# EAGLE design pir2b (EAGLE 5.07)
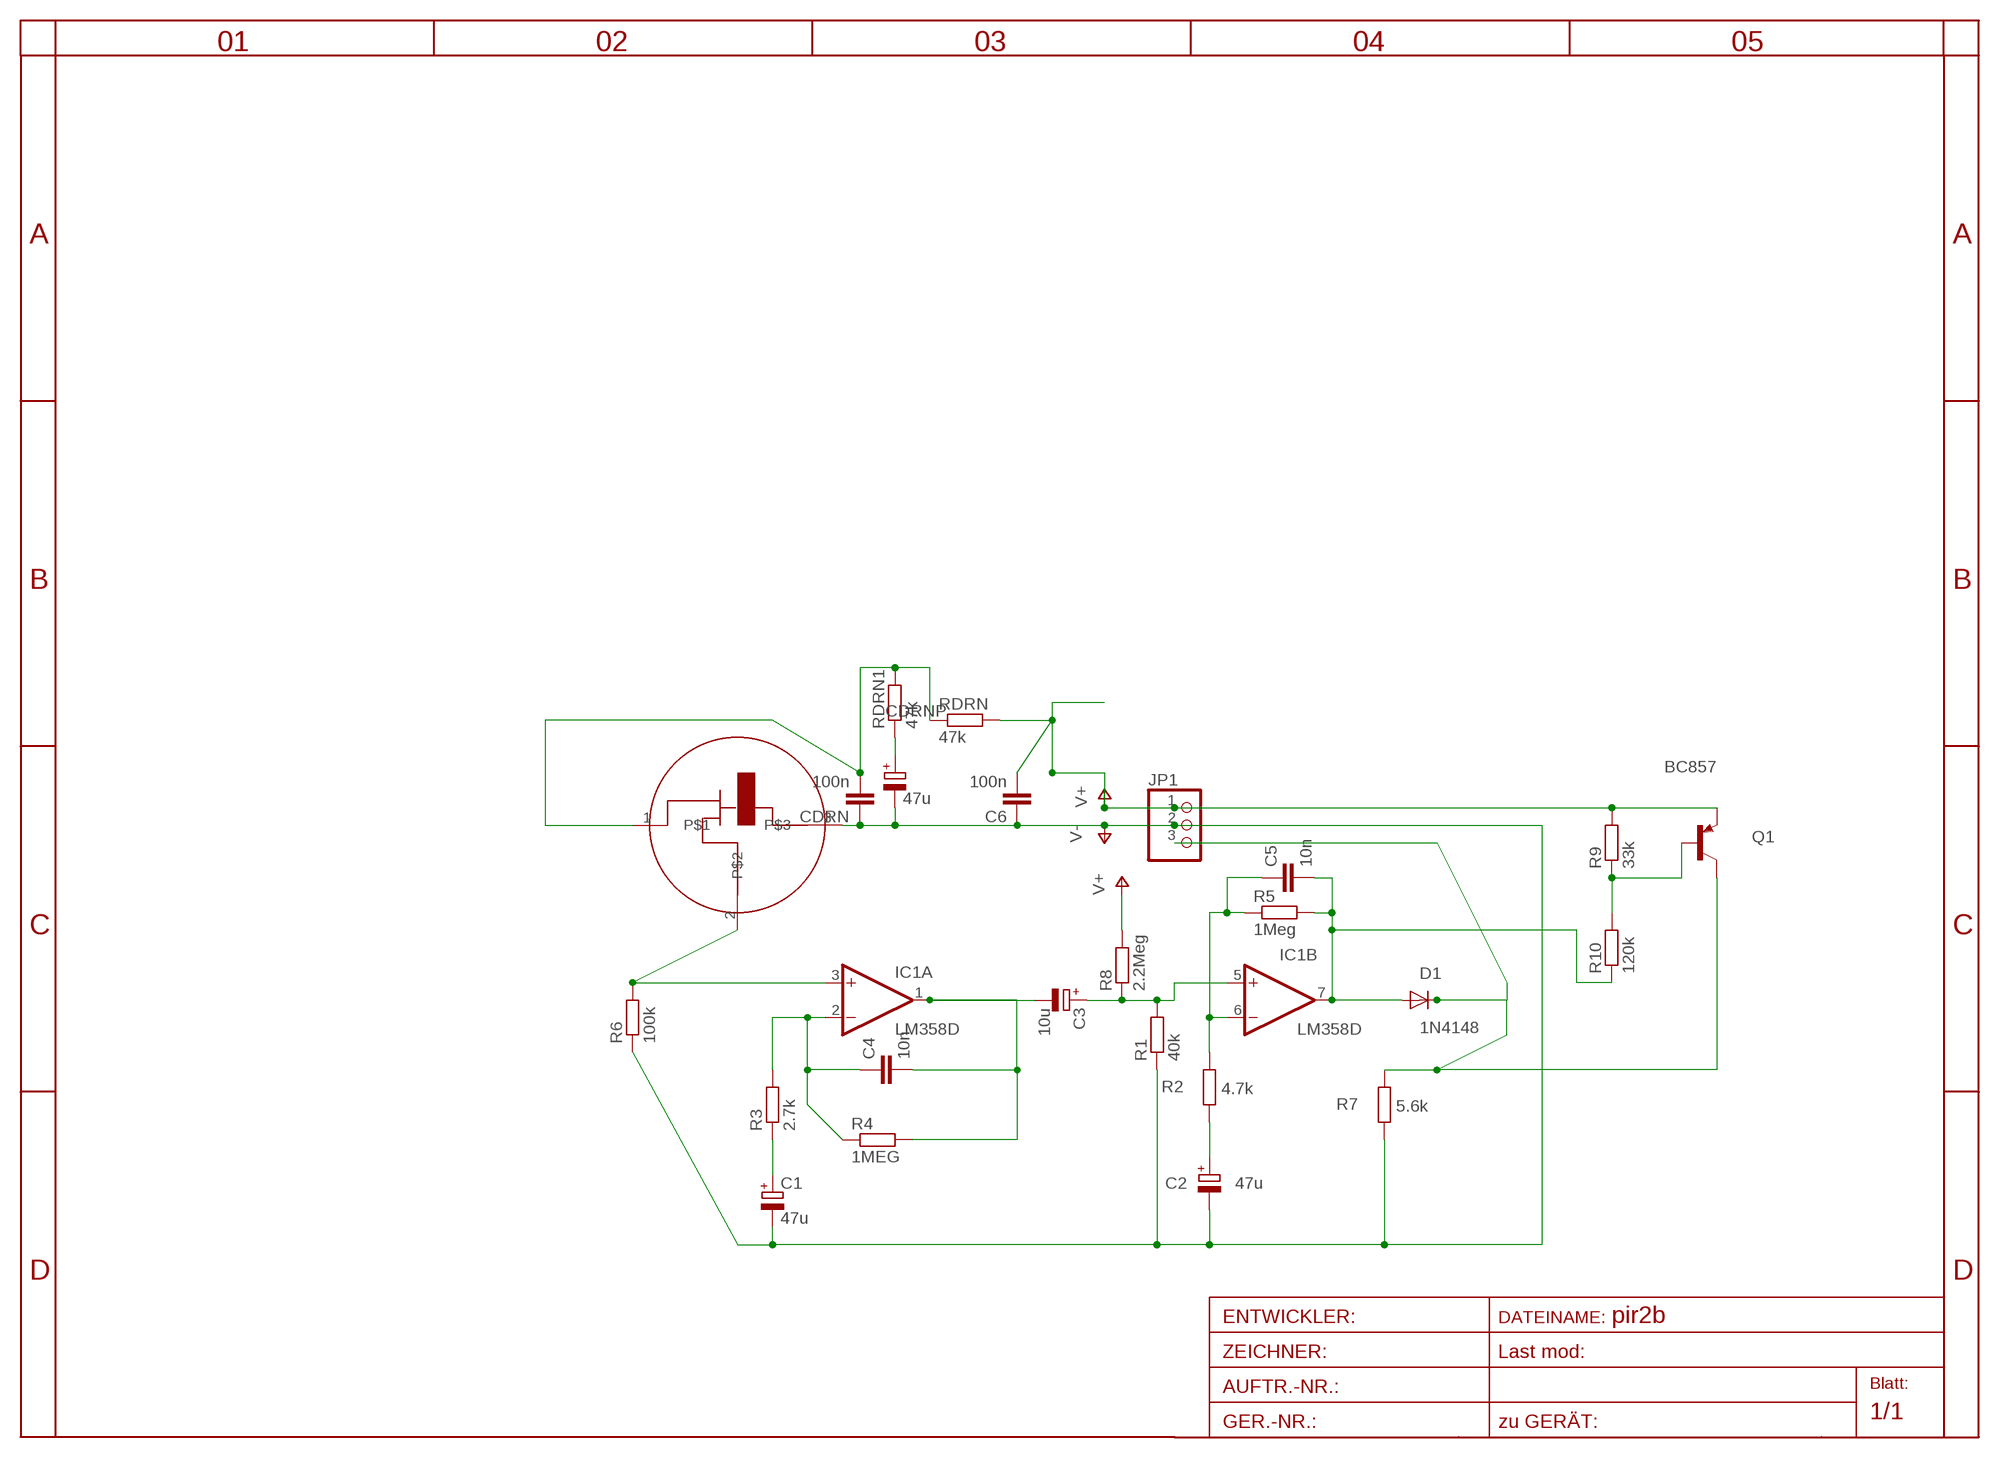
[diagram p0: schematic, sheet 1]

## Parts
C1  47u  CPOL-EUTT2D4L  [TT2D4L]
C2  47u  CPOL-EUTT24LR  [TT24LR]
C3  10u  CPOL-EUTT24LR  [TT24LR]
C4  10n  C-EUC0805  [C0805]
C5  10n  C-EUC0805  [C0805]
C6  100n  C-EUC0805  [C0805]
CDRN  100n  C-EUC0805  [C0805]
CDRNP  47u  CPOL-EUTT2D4L  [TT2D4L]
D1  1N4148  1N4148MINIMELF  [MINIMELF]
IC1  LM358D  [SO08]
JP1  PINHD-1X3  [1X03]
PIR  RE200B  [R200B]
Q1  BC857  BC857ALT1SMD  [SOT23-BEC]
R1  40k  R-EU_R0805  [R0805]
R2  4.7k  R-EU_R0805  [R0805]
R3  2.7k  R-EU_R1206  [R1206]
R4  1MEG  R-EU_R0805  [R0805]
R5  1Meg  R-EU_R0805  [R0805]
R6  100k  R-EU_R0805  [R0805]
R7  5.6k  R-EU_R0805  [R0805]
R8  2.2Meg  R-EU_R0805  [R0805]
R9  33k  R-EU_R0805  [R0805]
R10  120k  R-EU_R1206  [R1206]
RDRN  47k  R-EU_R0805  [R0805]
RDRN1  47k  R-EU_R0805  [R0805]

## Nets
DRN: CDRN.2 PIR.1 RDRN1.2 RDRN.1
N$1: C5.2 D1.A IC1.7(B:OUT) R5.2 R10.1
N$3: CDRNP.+ RDRN1.1
N$4: IC1.3(A:+IN) PIR.2 R6.2
N$5: C4.1 IC1.2(A:-IN) R3.2 R4.1
N$6: C1.+ R3.1
N$7: C3.- C4.2 IC1.1(A:OUT) R4.2
N$8: C3.+ IC1.5(B:+IN) R1.2 R8.1
N$9: C5.1 IC1.6(B:-IN) R2.2 R5.1
N$10: C2.+ R2.1
N$12: Q1.B R9.1 R10.2
SIGNAL: D1.C JP1.3 Q1.C R7.2
V+: C6.2 JP1.1 Q1.E R8.2 R9.2 RDRN.2
V-: C1.- C2.- C6.1 CDRN.1 CDRNP.- JP1.2 PIR.3 R1.1 R6.1 R7.1

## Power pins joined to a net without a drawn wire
V+: IC1.8(P:V+)
V-: IC1.4(P:V-)

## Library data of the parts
C1-C3 CDRNP = rcl:CPOL-EU: POLARIZED CAPACITOR, European symbol
C4-C6 CDRN = rcl:C-EU: CAPACITOR, European symbol
D1 = diode-1:1N4148: DIODE
IC1 = linear:LM358: OP AMP also LM158; LM258; LM2904 Source: http://cache.national.com/ds/LM/LM158.pdf
JP1 = pinhead:PINHD-1X3: PIN HEADER
PIR = photo-elements:RE200B
Q1 = transistor-pnp:BC857*: PNP Transistror
R1-R10 RDRN RDRN1 = rcl:R-EU_: RESISTOR, European symbol

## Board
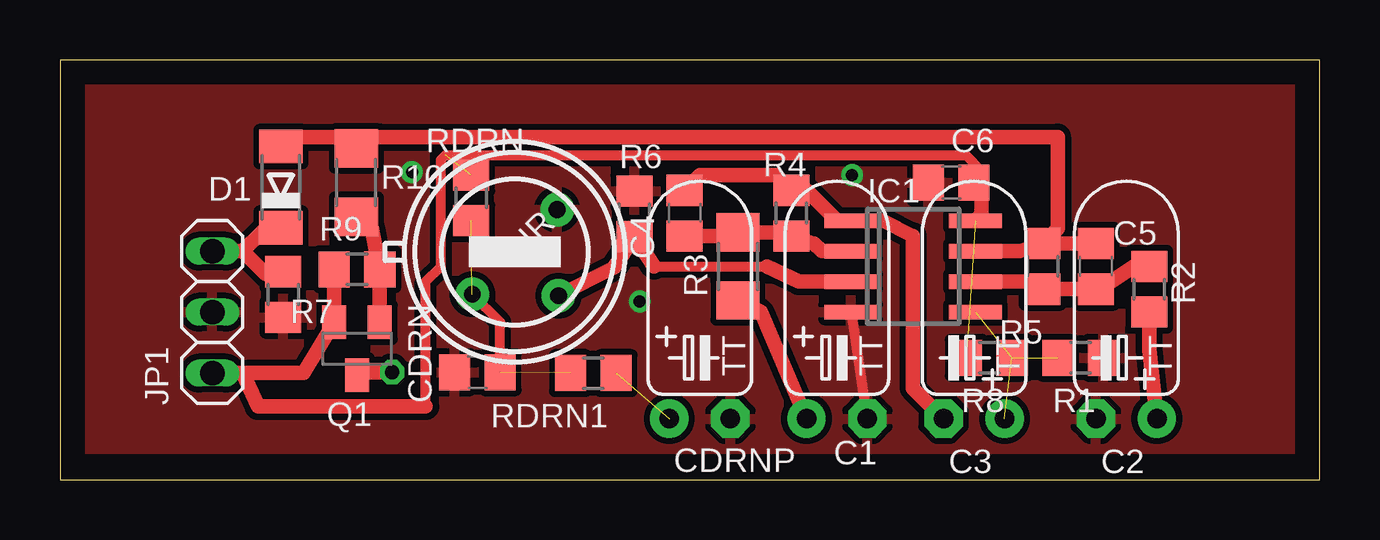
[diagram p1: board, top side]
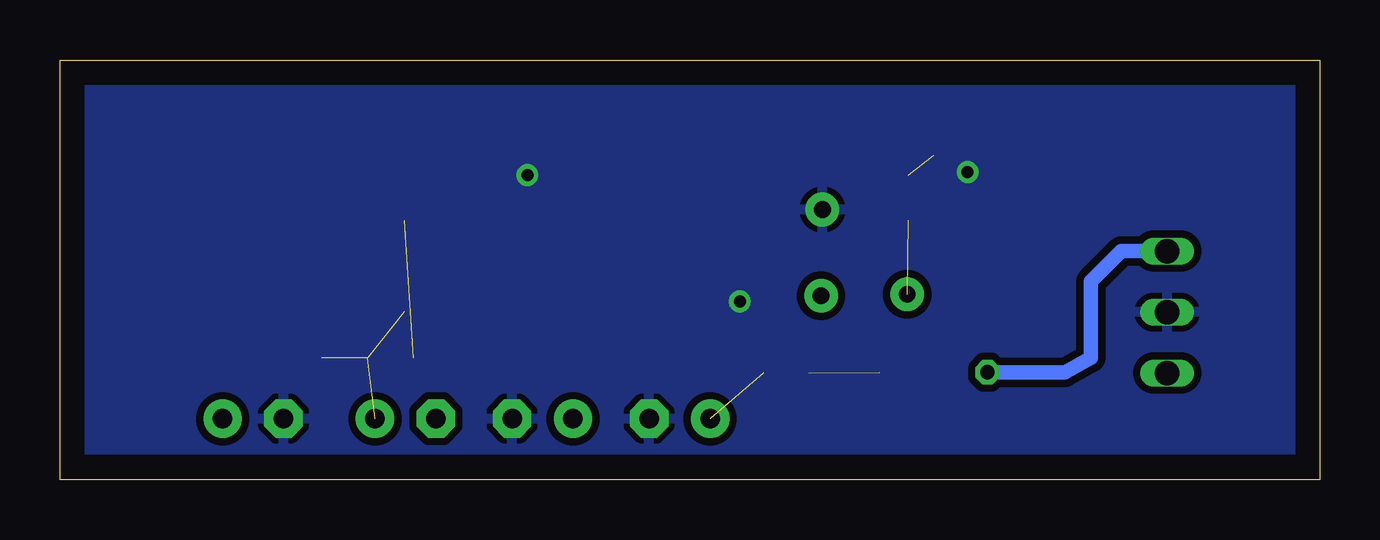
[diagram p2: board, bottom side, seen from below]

Size 52.5 x 17.5 mm. Coordinates in mm from the lower left corner, seen from the top.
Outline: 0,0 52.5,0 52.5,17.5 0,17.5 0,0
Copper layers (1*16): Top 0.035mm / dielectric 1.5mm / Bottom 0.035mm
Design rules "default": minimum track width 10mil, minimum drill 20mil, track to track 8mil, track to pad 8mil, pad to pad 8mil, via to via 8mil, smd to smd 8mil, copper to edge 40mil, drill to drill 8mil, minimum pad ring 1mil, minimum via ring 8mil, stop-mask expansion 4mil, vias tented up to drill 0mil, thermal gap 10mil

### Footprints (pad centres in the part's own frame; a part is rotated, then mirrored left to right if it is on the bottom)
TT2D4L = drill 0.813 pad 1.6 round: + -1.27,0 | drill 0.813 pad 1.6 octagon: - 1.27,0
TT24LR = drill 0.813 pad 1.6 round: + -1.27,0 | drill 0.813 pad 1.6 octagon: - 1.27,0
C0805 = smd 1.3 x 1.5: 1 -0.95,0; 2 0.95,0
MINIMELF = smd 1.4 x 1.8: A 1.7,0; C -1.7,0
SO08 = smd 0.6 x 2.2: 1 -1.905,-2.6; 2 -0.635,-2.6; 3 0.635,-2.6; 4 1.905,-2.6; 5 1.905,2.6; 6 0.635,2.6; 7 -0.635,2.6; 8 -1.905,2.6
1X03 = drill 1.016 long: 1 -2.54,0; 2 0,0; 3 2.54,0
R200B = drill 0.7 pad 1.4 round: 1 -2.5,0; 2 0,-2.58; 3 2.5,0
SOT23-BEC = smd 1 x 1.4: B -0.95,-1.1; C 0,1.1; E 0.95,-1.1
R0805 = smd 1.3 x 1.5: 1 -0.95,0; 2 0.95,0
R1206 = smd 1.6 x 1.803: 1 -1.422,0; 2 1.422,0

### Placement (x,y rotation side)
C1  32.38,2.54 0 top
C2  44.45,2.54 180 top
C3  38.1,2.54 180 top
C4  26.04,11.11 90 top
C5  43.18,8.89 90 top
C6  37.15,12.38 0 top
CDRN  17.4,4.48 0 top
CDRNP  26.67,2.54 0 top
D1  9.21,12.19 90 top
IC1  35.56,8.89 270 top
JP1  6.35,6.99 90 top
PIR  18.95,9.49 45 top
Q1  12.38,5.46 180 top
R1  42.55,5.08 180 top
R2  45.4,7.94 90 top
R3  28.26,8.89 90 top
R4  30.48,11.11 90 top
R5  40.96,8.89 90 top
R6  23.94,11.08 270 top
R7  9.3,7.72 90 top
R8  38.73,5.08 180 top
R9  12.38,8.76 180 top
R10  12.35,12.38 270 top
RDRN  17.14,11.75 90 top
RDRN1  22.23,4.45 180 top

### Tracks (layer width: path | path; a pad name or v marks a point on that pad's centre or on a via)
DRN  (2 unrouted)
  Top 0.406: CDRN.2 18.35,6.56 PIR.1
N$1
  Top 0.406: R5.2 | 13.34,14.29 R10.1
  Top 0.61: C5.2 R5.2 41.59,10.47 41.59,14.29 13.34,14.29 9.96,14.29 D1.A | R5.2 40.01,9.53 IC1.7
N$3  (1 unrouted)
N$4
  Top 0.406: 24.77,8.89 29.46,8.89
  Top 0.61: PIR.2 23.1,8.85 R6.2 24.77,8.89 | IC1.3 30.8,8.26 29.46,8.89
N$5
  Top 0.61: C4.1 27.55,10.16 R3.2 29.8,10.31 R4.1 31.43,9.85 31.75,9.53 IC1.2
N$6
  Top 0.61: C1.+ 29.21,6.99 R3.1
N$7
  Top 0.406: 32.38,10.79 IC1.1 | 31.11,12.06 30.8,12.06 R4.2
  Top 0.61: C3.- 35.56,3.81 35.56,10.16 34.29,10.79 IC1.1 | 31.11,12.06 32.38,10.79 | C4.2 26.67,12.7 29.84,12.7 R4.2
N$8  (3 unrouted)
N$9
  Top 0.406: 40.64,8.26 R5.1 | C5.1 43.5,7.94 43.81,8.26 | 44.77,8.89 R2.2
  Top 0.61: IC1.6 40.64,8.26 | R5.1 C5.1 | 43.81,8.26 44.77,8.89
N$10
  Top 0.61: C2.+ 45.4,5.4 R2.1
N$12
  Top 0.61: Q1.B R9.1 12.98,10.52 R10.2
SIGNAL  (via drill 0.6)
  Top 0.61: Q1.C 12.58,4.46 v13.84,4.48 | R7.2 8.57,8.57 7.62,9.53 | JP1.3 7.62,9.53 | D1.C 8.46,10.37 7.62,9.53
  Bottom 0.61: v13.84,4.48 10.6,4.48 9.53,5.08 9.53,8.26 8.26,9.53 JP1.3
V+  (2 unrouted)
  Top 0.406: 38.41,12.38 38.41,12.86 37.75,13.53 16.07,13.53 15.88,13.34 15.88,8.89 15.24,8.26 15.24,3.05
  Top 0.61: 7.62,4.45 8.26,3.05 15.24,3.05 | JP1.1 7.62,4.45 | 7.62,4.45 10.16,4.45 Q1.E R9.2 | C6.2 38.41,12.38 38.41,11.05 IC1.8
V-  (via drill 0.5)
  Top 0.406: C1.- 33.02,6.92 IC1.4
  other vias: 33.02,12.7 24.16,7.43 14.67,12.83
  pour Top (isolate 0.254, rank 2): 0.64,16.51 52.07,16.51 52.07,1.27 0.64,1.27
  pour Bottom (isolate 0.305): 0.64,16.51 52.07,16.51 52.07,1.27 0.64,1.27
